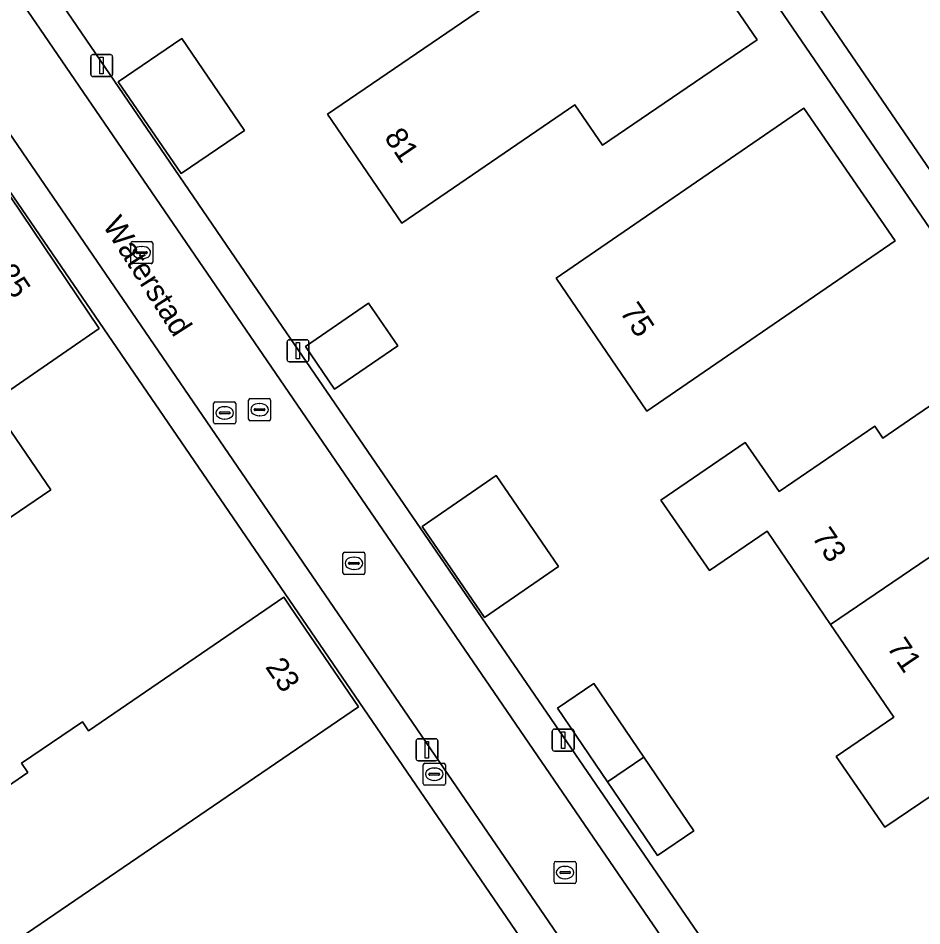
# Model space of a CAD drawing. Extents: x 155275 to 156265, y 382654 to 383635.
# Drawn here: x 155646.86 to 155687.84, y 383354.97 to 383396.14 of the extents above; entities that cross this region are included whole.
import ezdxf

# ---------------------------------------------------------------- set-up
doc = ezdxf.new("R2010")
doc.units = 0
for name, color, linetype in [('IMGEO_Brandkraan', 7, 'Continuous'), ('IMGEO_Erf', 7, 'Continuous'), ('IMGEO_Groenvoorziening', 7, 'Continuous'), ('IMGEO_Kolk', 7, 'Continuous'), ('IMGEO_Lichtmast', 7, 'Continuous'), ('IMGEO_Openbare_ruimte_label', 7, 'Continuous'), ('IMGEO_Pand', 7, 'Continuous'), ('IMGEO_Pand_nummerreeks', 7, 'Continuous'), ('IMGEO_Rijbaan_lokaal_open', 7, 'Continuous'), ('IMGEO_Rioolput', 7, 'Continuous'), ('IMGEO_Voetpad_open', 7, 'Continuous')]:
    doc.layers.add(name, color=color, linetype=linetype)

msp = doc.modelspace()

# ---------------------------------------------------------------- linework, layer by layer
at = {"layer": 'IMGEO_Brandkraan'}
for p, q in [((155665.23, 383361.42), (155665.23, 383362.272)), ((155665.305, 383362.346), (155666.157, 383362.346)), ((155665.718, 383362.126), (155665.743, 383362.126)), ((155666.231, 383362.272), (155666.231, 383361.42)), ((155665.489, 383361.84), (155665.489, 383361.852)), ((155665.927, 383361.803), (155665.529, 383361.803)), ((155665.532, 383361.889), (155665.93, 383361.889)), ((155665.973, 383361.852), (155665.973, 383361.84)), ((155666.157, 383361.346), (155665.305, 383361.346)), ((155665.741, 383361.566), (155665.716, 383361.566))]:
    msp.add_line(p, q, dxfattribs=at)
for points in [[(155665.23, 383361.42), (155665.23, 383362.272)], [(155665.305, 383362.346), (155666.157, 383362.346)], [(155666.231, 383362.272), (155666.231, 383361.42)], [(155666.157, 383361.346), (155665.305, 383361.346)]]:
    msp.add_lwpolyline(points, dxfattribs=at)
for centre, radius, start, end in [((155665.307, 383362.27), 0.0765, 91.552, 178.448), ((155665.307, 383362.27), 0.0765, 91.552, 178.448), ((155666.155, 383362.27), 0.0765, 1.552, 88.448), ((155666.155, 383362.27), 0.0765, 1.552, 88.448), ((155665.529, 383361.849), 0.0403, 85.8775, 175.7526), ((155665.526, 383361.839), 0.0366, 178.938, 274.7102), ((155665.93, 383361.846), 0.043, 264.8664, 352.4533), ((155665.934, 383361.851), 0.0386, 1.7309, 96.639), ((155665.307, 383361.422), 0.0765, 181.552, 268.448), ((155665.307, 383361.422), 0.0765, 181.552, 268.448), ((155666.155, 383361.422), 0.0765, 271.552, 358.448), ((155666.155, 383361.422), 0.0765, 271.552, 358.448)]:
    msp.add_arc(centre, radius, start, end, dxfattribs=at)
for centre, major_axis, ratio, start_param, end_param in [((155665.717, 383361.846), (-0.387, 0.002), 0.722429, 4.712389, 7.853982), ((155665.742, 383361.846), (-0.39, 0.002), 0.717154, 1.570796, 4.712389)]:
    msp.add_ellipse(centre, major_axis=major_axis, ratio=ratio, start_param=start_param, end_param=end_param, dxfattribs=at)
at = {"layer": 'IMGEO_Erf'}
for points in [[(155657.299, 383431.777), (155657.022, 383432.185), (155634.905, 383417.186), (155657.35, 383384.321), (155685.798, 383342.799), (155707.917, 383357.778), (155706.87, 383359.32)], [(155626.344, 383411.364), (155605.932, 383397.438), (155603.987, 383396.057), (155605.754, 383393.471), (155605.827, 383393.52), (155653.992, 383322.86), (155654.882, 383321.57), (155677.497, 383337.038), (155680.25, 383338.906), (155654.839, 383376.063), (155629.299, 383413.395)], [(155664.262, 383386.851), (155660.887, 383391.796), (155675.749, 383401.941), (155680.373, 383395.166), (155673.358, 383390.385), (155672.109, 383392.206)], [(155654.245, 383389.095), (155651.394, 383393.258), (155654.285, 383395.225), (155657.124, 383391.055)], [(155682.494, 383392.068), (155686.631, 383386.042), (155675.363, 383378.324), (155671.25, 383384.356)], [(155632.183, 383363.753), (155632.091, 383363.899), (155632.39, 383364.102), (155630.323, 383367.106), (155630.036, 383366.909), (155627.855, 383370.095), (155632.678, 383373.378), (155633.279, 383372.507), (155634.699, 383373.478), (155644.215, 383379.981), (155641.198, 383384.398), (155646.515, 383388.036), (155650.539, 383382.066), (155645.636, 383378.694), (155648.345, 383374.745)], [(155664.07, 383381.278), (155661.206, 383379.32), (155659.882, 383381.255), (155662.749, 383383.21)], [(155676.001, 383374.285), (155679.826, 383376.894), (155681.363, 383374.67), (155685.708, 383377.643), (155686.078, 383377.098), (155687.286, 383377.925), (155690.617, 383380.203), (155693.821, 383375.522), (155695.296, 383373.366), (155695.031, 383373.186), (155696.707, 383370.712), (155693.642, 383368.618), (155692.452, 383367.806), (155692.81, 383367.255), (155688.46, 383364.27), (155689.99, 383362.038), (155686.157, 383359.44), (155683.96, 383362.652), (155686.568, 383364.436), (155683.705, 383368.644), (155680.832, 383372.872), (155678.207, 383371.082)], [(155668.529, 383375.397), (155671.368, 383371.269), (155668.001, 383368.953), (155665.175, 383373.09)], [(155647.303, 383361.927), (155647.013, 383362.352), (155649.769, 383364.231), (155650.055, 383363.812), (155658.911, 383369.873), (155659.212, 383369.426), (155662.297, 383364.905), (155645.369, 383353.349), (155644.717, 383354.302), (155643.781, 383353.657), (155643.882, 383353.509), (155641.508, 383351.891), (155638.669, 383356.028), (155637.151, 383358.24), (155637.284, 383358.325), (155636.638, 383359.304), (155639.894, 383361.521), (155641.364, 383360.503), (155643.288, 383359.179)], [(155672.969, 383365.966), (155675.238, 383362.624), (155677.508, 383359.282), (155675.853, 383358.158), (155673.584, 383361.5), (155671.314, 383364.843)]]:
    msp.add_lwpolyline(points, close=True, dxfattribs=at)
at = {"layer": 'IMGEO_Groenvoorziening'}
msp.add_lwpolyline([(155671.715, 383413.396), (155689.641, 383387.16), (155697.682, 383392.701), (155680.127, 383418.418), (155674.678, 383414.539), (155674.299, 383415.086)], close=True, dxfattribs=at)
at = {"layer": 'IMGEO_Kolk'}
for p, q in [((155652.039, 383386.008), (155652.891, 383386.008)), ((155651.964, 383385.082), (155651.964, 383385.934)), ((155652.452, 383385.788), (155652.477, 383385.788)), ((155652.965, 383385.934), (155652.965, 383385.082)), ((155652.223, 383385.502), (155652.223, 383385.514)), ((155652.661, 383385.465), (155652.263, 383385.465)), ((155652.266, 383385.551), (155652.664, 383385.551)), ((155652.475, 383385.228), (155652.45, 383385.228)), ((155652.707, 383385.514), (155652.707, 383385.502)), ((155652.891, 383385.008), (155652.039, 383385.008)), ((155661.586, 383370.989), (155661.586, 383371.841)), ((155661.661, 383371.915), (155662.513, 383371.915)), ((155662.074, 383371.695), (155662.099, 383371.695)), ((155662.587, 383371.841), (155662.587, 383370.989)), ((155661.845, 383371.409), (155661.845, 383371.421)), ((155662.283, 383371.372), (155661.885, 383371.372)), ((155661.888, 383371.458), (155662.286, 383371.458)), ((155662.329, 383371.421), (155662.329, 383371.409)), ((155662.513, 383370.915), (155661.661, 383370.915)), ((155662.097, 383371.135), (155662.072, 383371.135)), ((155671.161, 383356.963), (155671.161, 383357.815)), ((155671.236, 383357.889), (155672.088, 383357.889)), ((155671.649, 383357.669), (155671.674, 383357.669)), ((155672.162, 383357.815), (155672.162, 383356.963)), ((155671.42, 383357.383), (155671.42, 383357.395)), ((155671.858, 383357.346), (155671.46, 383357.346)), ((155671.463, 383357.432), (155671.861, 383357.432)), ((155671.904, 383357.395), (155671.904, 383357.383)), ((155672.088, 383356.889), (155671.236, 383356.889)), ((155671.672, 383357.109), (155671.647, 383357.109))]:
    msp.add_line(p, q, dxfattribs=at)
for points in [[(155652.039, 383386.008), (155652.891, 383386.008)], [(155651.964, 383385.082), (155651.964, 383385.934)], [(155652.965, 383385.934), (155652.965, 383385.082)], [(155652.891, 383385.008), (155652.039, 383385.008)], [(155661.586, 383370.989), (155661.586, 383371.841)], [(155661.661, 383371.915), (155662.513, 383371.915)], [(155662.587, 383371.841), (155662.587, 383370.989)], [(155662.513, 383370.915), (155661.661, 383370.915)], [(155671.161, 383356.963), (155671.161, 383357.815)], [(155671.236, 383357.889), (155672.088, 383357.889)], [(155672.162, 383357.815), (155672.162, 383356.963)], [(155672.088, 383356.889), (155671.236, 383356.889)]]:
    msp.add_lwpolyline(points, dxfattribs=at)
for centre, radius, start, end in [((155652.041, 383385.932), 0.0765, 91.552, 178.448), ((155652.041, 383385.932), 0.0765, 91.552, 178.448), ((155652.889, 383385.932), 0.0765, 1.552, 88.448), ((155652.889, 383385.932), 0.0765, 1.552, 88.448), ((155652.263, 383385.511), 0.0403, 85.8775, 175.7526), ((155652.26, 383385.501), 0.0366, 178.938, 274.7102), ((155652.664, 383385.508), 0.043, 264.8664, 352.4533), ((155652.668, 383385.513), 0.0386, 1.7309, 96.639), ((155652.041, 383385.084), 0.0765, 181.552, 268.448), ((155652.041, 383385.084), 0.0765, 181.552, 268.448), ((155652.889, 383385.084), 0.0765, 271.552, 358.448), ((155652.889, 383385.084), 0.0765, 271.552, 358.448), ((155661.663, 383371.839), 0.0765, 91.552, 178.448), ((155661.663, 383371.839), 0.0765, 91.552, 178.448), ((155662.511, 383371.839), 0.0765, 1.552, 88.448), ((155662.511, 383371.839), 0.0765, 1.552, 88.448), ((155661.885, 383371.418), 0.0403, 85.8775, 175.7526), ((155661.882, 383371.408), 0.0366, 178.938, 274.7102), ((155662.286, 383371.415), 0.043, 264.8664, 352.4533), ((155662.29, 383371.42), 0.0386, 1.7309, 96.639), ((155661.663, 383370.991), 0.0765, 181.552, 268.448), ((155661.663, 383370.991), 0.0765, 181.552, 268.448), ((155662.511, 383370.991), 0.0765, 271.552, 358.448), ((155662.511, 383370.991), 0.0765, 271.552, 358.448), ((155671.238, 383357.813), 0.0765, 91.552, 178.448), ((155671.238, 383357.813), 0.0765, 91.552, 178.448), ((155672.086, 383357.813), 0.0765, 1.552, 88.448), ((155672.086, 383357.813), 0.0765, 1.552, 88.448), ((155671.46, 383357.392), 0.0403, 85.8775, 175.7526), ((155671.457, 383357.382), 0.0366, 178.938, 274.7102), ((155671.861, 383357.389), 0.043, 264.8664, 352.4533), ((155671.865, 383357.394), 0.0386, 1.7309, 96.639), ((155671.238, 383356.965), 0.0765, 181.552, 268.448), ((155671.238, 383356.965), 0.0765, 181.552, 268.448), ((155672.086, 383356.965), 0.0765, 271.552, 358.448), ((155672.086, 383356.965), 0.0765, 271.552, 358.448)]:
    msp.add_arc(centre, radius, start, end, dxfattribs=at)
for centre, major_axis, ratio, start_param, end_param in [((155652.451, 383385.508), (-0.387, 0.002), 0.722429, 4.712389, 7.853982), ((155652.476, 383385.508), (-0.39, 0.002), 0.717154, 1.570796, 4.712389), ((155662.073, 383371.415), (-0.387, 0.002), 0.722429, 4.712389, 7.853982), ((155662.098, 383371.415), (-0.39, 0.002), 0.717154, 1.570796, 4.712389), ((155671.648, 383357.389), (-0.387, 0.002), 0.722429, 4.712389, 7.853982), ((155671.673, 383357.389), (-0.39, 0.002), 0.717154, 1.570796, 4.712389)]:
    msp.add_ellipse(centre, major_axis=major_axis, ratio=ratio, start_param=start_param, end_param=end_param, dxfattribs=at)
at = {"layer": 'IMGEO_Lichtmast'}
for p, q in [((155650.15, 383393.596), (155650.15, 383394.396)), ((155650.15, 383394.396), (155650.15, 383393.596)), ((155650.25, 383394.496), (155651.04, 383394.496)), ((155651.04, 383394.496), (155650.25, 383394.496)), ((155651.14, 383394.396), (155651.14, 383393.596)), ((155651.14, 383393.596), (155651.14, 383394.396)), ((155651.04, 383393.496), (155650.25, 383393.496)), ((155650.25, 383393.496), (155651.04, 383393.496)), ((155659.052, 383380.659), (155659.052, 383381.459)), ((155659.052, 383381.459), (155659.052, 383380.659)), ((155659.152, 383381.559), (155659.942, 383381.559)), ((155659.942, 383381.559), (155659.152, 383381.559)), ((155660.042, 383381.459), (155660.042, 383380.659)), ((155660.042, 383380.659), (155660.042, 383381.459)), ((155659.942, 383380.559), (155659.152, 383380.559)), ((155659.152, 383380.559), (155659.942, 383380.559)), ((155671.079, 383362.994), (155671.079, 383363.794)), ((155671.079, 383363.794), (155671.079, 383362.994)), ((155671.179, 383363.894), (155671.969, 383363.894)), ((155671.969, 383363.894), (155671.179, 383363.894)), ((155672.069, 383363.794), (155672.069, 383362.994)), ((155672.069, 383362.994), (155672.069, 383363.794)), ((155664.902, 383362.556), (155664.902, 383363.356)), ((155664.902, 383363.356), (155664.902, 383362.556)), ((155665.002, 383363.456), (155665.792, 383363.456)), ((155665.792, 383363.456), (155665.002, 383363.456)), ((155665.892, 383363.356), (155665.892, 383362.556)), ((155665.892, 383362.556), (155665.892, 383363.356)), ((155671.969, 383362.894), (155671.179, 383362.894)), ((155671.179, 383362.894), (155671.969, 383362.894)), ((155665.792, 383362.456), (155665.002, 383362.456)), ((155665.002, 383362.456), (155665.792, 383362.456))]:
    msp.add_line(p, q, dxfattribs=at)
for points in [[(155650.57, 383394.371), (155650.72, 383394.371), (155650.72, 383393.621), (155650.57, 383393.621), (155650.57, 383394.371)], [(155659.472, 383381.434), (155659.622, 383381.434), (155659.622, 383380.684), (155659.472, 383380.684), (155659.472, 383381.434)], [(155671.499, 383363.769), (155671.649, 383363.769), (155671.649, 383363.019), (155671.499, 383363.019), (155671.499, 383363.769)], [(155665.322, 383363.331), (155665.472, 383363.331), (155665.472, 383362.581), (155665.322, 383362.581), (155665.322, 383363.331)]]:
    msp.add_lwpolyline(points, dxfattribs=at)
for centre, start, end in [((155650.25, 383394.396), 90, 180), ((155650.25, 383394.396), 90, 180), ((155651.04, 383394.396), 0, 90), ((155651.04, 383394.396), 360, 90), ((155650.25, 383393.596), 180, 270), ((155650.25, 383393.596), 180, 270), ((155651.04, 383393.596), 270, 0), ((155651.04, 383393.596), 270, 0), ((155659.152, 383381.459), 90, 180), ((155659.152, 383381.459), 90, 180), ((155659.942, 383381.459), 0, 90), ((155659.942, 383381.459), 360, 90), ((155659.152, 383380.659), 180, 270), ((155659.152, 383380.659), 180, 270), ((155659.942, 383380.659), 270, 0), ((155659.942, 383380.659), 270, 0), ((155671.179, 383363.794), 90, 180), ((155671.179, 383363.794), 90, 180), ((155671.969, 383363.794), 0, 90), ((155671.969, 383363.794), 360, 90), ((155665.002, 383363.356), 90, 180), ((155665.002, 383363.356), 90, 180), ((155665.792, 383363.356), 0, 90), ((155665.792, 383363.356), 360, 90), ((155671.179, 383362.994), 180, 270), ((155671.179, 383362.994), 180, 270), ((155671.969, 383362.994), 270, 0), ((155671.969, 383362.994), 270, 0), ((155665.002, 383362.556), 180, 270), ((155665.002, 383362.556), 180, 270), ((155665.792, 383362.556), 270, 0), ((155665.792, 383362.556), 270, 0)]:
    msp.add_arc(centre, 0.1, start, end, dxfattribs=at)
at = {"layer": 'IMGEO_Pand'}
for points in [[(155675.749, 383401.941), (155660.887, 383391.796), (155664.262, 383386.851), (155672.109, 383392.206), (155673.358, 383390.385), (155680.373, 383395.166)], [(155654.285, 383395.225), (155651.394, 383393.258), (155654.245, 383389.095), (155657.124, 383391.055)], [(155682.494, 383392.068), (155671.25, 383384.356), (155675.363, 383378.324), (155686.631, 383386.042)], [(155645.636, 383378.694), (155650.539, 383382.066), (155646.515, 383388.036), (155641.198, 383384.398), (155644.215, 383379.981), (155634.699, 383373.478), (155633.279, 383372.507), (155632.678, 383373.378), (155627.855, 383370.095), (155630.036, 383366.909), (155630.323, 383367.106), (155632.39, 383364.102), (155632.091, 383363.899), (155632.183, 383363.753), (155648.345, 383374.745)], [(155662.749, 383383.21), (155659.882, 383381.255), (155661.206, 383379.32), (155664.07, 383381.278)], [(155690.617, 383380.203), (155687.286, 383377.925), (155686.078, 383377.098), (155685.708, 383377.643), (155681.363, 383374.67), (155679.826, 383376.894), (155676.001, 383374.285), (155678.207, 383371.082), (155680.832, 383372.872), (155683.705, 383368.644), (155693.821, 383375.522)], [(155668.529, 383375.397), (155665.175, 383373.09), (155668.001, 383368.953), (155671.368, 383371.269)], [(155696.707, 383370.712), (155695.031, 383373.186), (155695.296, 383373.366), (155693.821, 383375.522), (155683.705, 383368.644), (155686.568, 383364.436), (155683.96, 383362.652), (155686.157, 383359.44), (155689.99, 383362.038), (155688.46, 383364.27), (155692.81, 383367.255), (155692.452, 383367.806), (155693.642, 383368.618)], [(155662.297, 383364.905), (155659.212, 383369.426), (155658.911, 383369.873), (155650.055, 383363.812), (155649.769, 383364.231), (155647.013, 383362.352), (155647.303, 383361.927), (155643.288, 383359.179), (155641.364, 383360.503), (155639.894, 383361.521), (155636.638, 383359.304), (155637.284, 383358.325), (155637.151, 383358.24), (155638.669, 383356.028), (155641.508, 383351.891), (155643.882, 383353.509), (155643.781, 383353.657), (155644.717, 383354.302), (155645.369, 383353.349)], [(155671.314, 383364.843), (155673.584, 383361.5), (155675.238, 383362.624), (155672.969, 383365.966)], [(155675.238, 383362.624), (155673.584, 383361.5), (155675.853, 383358.158), (155677.508, 383359.282)]]:
    msp.add_lwpolyline(points, close=True, dxfattribs=at)
at = {"layer": 'IMGEO_Rijbaan_lokaal_open'}
for points in [[(155629.214, 383416.139), (155630.534, 383414.209), (155681.461, 383339.737), (155682.726, 383337.887)], [(155685.887, 383340.048), (155684.569, 383341.975), (155633.677, 383416.365)]]:
    msp.add_lwpolyline(points, dxfattribs=at)
at = {"layer": 'IMGEO_Rioolput'}
for p, q in [((155655.724, 383377.811), (155655.724, 383378.663)), ((155655.799, 383378.737), (155656.651, 383378.737)), ((155656.725, 383378.663), (155656.725, 383377.811)), ((155657.308, 383377.959), (155657.308, 383378.811)), ((155657.383, 383378.885), (155658.235, 383378.885)), ((155657.796, 383378.665), (155657.821, 383378.665)), ((155658.309, 383378.811), (155658.309, 383377.959)), ((155655.983, 383378.231), (155655.983, 383378.243)), ((155656.421, 383378.194), (155656.023, 383378.194)), ((155656.026, 383378.28), (155656.424, 383378.28)), ((155656.212, 383378.517), (155656.237, 383378.517)), ((155656.467, 383378.243), (155656.467, 383378.231)), ((155657.567, 383378.379), (155657.567, 383378.391)), ((155658.005, 383378.342), (155657.607, 383378.342)), ((155657.61, 383378.428), (155658.008, 383378.428)), ((155658.051, 383378.391), (155658.051, 383378.379)), ((155656.235, 383377.957), (155656.21, 383377.957)), ((155658.235, 383377.885), (155657.383, 383377.885)), ((155657.819, 383378.105), (155657.794, 383378.105)), ((155656.651, 383377.737), (155655.799, 383377.737))]:
    msp.add_line(p, q, dxfattribs=at)
for points in [[(155655.724, 383377.811), (155655.724, 383378.663)], [(155655.799, 383378.737), (155656.651, 383378.737)], [(155656.725, 383378.663), (155656.725, 383377.811)], [(155657.308, 383377.959), (155657.308, 383378.811)], [(155657.383, 383378.885), (155658.235, 383378.885)], [(155658.309, 383378.811), (155658.309, 383377.959)], [(155658.235, 383377.885), (155657.383, 383377.885)], [(155656.651, 383377.737), (155655.799, 383377.737)]]:
    msp.add_lwpolyline(points, dxfattribs=at)
for centre, radius, start, end in [((155655.801, 383378.661), 0.0765, 91.552, 178.448), ((155655.801, 383378.661), 0.0765, 91.552, 178.448), ((155656.649, 383378.661), 0.0765, 1.552, 88.448), ((155656.649, 383378.661), 0.0765, 1.552, 88.448), ((155657.385, 383378.809), 0.0765, 91.552, 178.448), ((155657.385, 383378.809), 0.0765, 91.552, 178.448), ((155658.233, 383378.809), 0.0765, 1.552, 88.448), ((155658.233, 383378.809), 0.0765, 1.552, 88.448), ((155656.023, 383378.24), 0.0403, 85.8775, 175.7526), ((155656.02, 383378.23), 0.0366, 178.938, 274.7102), ((155656.424, 383378.237), 0.043, 264.8664, 352.4533), ((155656.428, 383378.242), 0.0386, 1.7309, 96.639), ((155657.607, 383378.388), 0.0403, 85.8775, 175.7526), ((155657.604, 383378.378), 0.0366, 178.938, 274.7102), ((155658.008, 383378.385), 0.043, 264.8664, 352.4533), ((155658.012, 383378.39), 0.0386, 1.7309, 96.639), ((155655.801, 383377.813), 0.0765, 181.552, 268.448), ((155655.801, 383377.813), 0.0765, 181.552, 268.448), ((155656.649, 383377.813), 0.0765, 271.552, 358.448), ((155656.649, 383377.813), 0.0765, 271.552, 358.448), ((155657.385, 383377.961), 0.0765, 181.552, 268.448), ((155657.385, 383377.961), 0.0765, 181.552, 268.448), ((155658.233, 383377.961), 0.0765, 271.552, 358.448), ((155658.233, 383377.961), 0.0765, 271.552, 358.448)]:
    msp.add_arc(centre, radius, start, end, dxfattribs=at)
for centre, major_axis, ratio, start_param, end_param in [((155657.795, 383378.385), (-0.387, 0.002), 0.722429, 4.712389, 7.853982), ((155657.82, 383378.385), (-0.39, 0.002), 0.717154, 1.570796, 4.712389), ((155656.211, 383378.237), (-0.387, 0.002), 0.722429, 4.712389, 7.853982), ((155656.236, 383378.237), (-0.39, 0.002), 0.717154, 1.570796, 4.712389)]:
    msp.add_ellipse(centre, major_axis=major_axis, ratio=ratio, start_param=start_param, end_param=end_param, dxfattribs=at)
at = {"layer": 'IMGEO_Voetpad_open'}
msp.add_lwpolyline([(155657.299, 383431.777), (155706.87, 383359.32), (155707.917, 383357.778), (155708.636, 383356.718), (155708.663, 383356.678), (155711.009, 383353.222), (155711.461, 383352.556), (155712.721, 383353.417), (155709.882, 383357.573), (155717.961, 383363.071), (155720.795, 383358.936), (155720.939, 383359.034), (155722.109, 383359.832), (155721.652, 383360.486), (155719.23, 383363.961), (155718.509, 383364.995), (155691.786, 383403.993)], dxfattribs=at)
for points in [[(155689.641, 383387.16), (155671.715, 383413.396), (155674.299, 383415.086), (155674.678, 383414.539), (155680.127, 383418.418), (155697.682, 383392.701)], [(155634.905, 383417.186), (155633.677, 383416.365), (155684.569, 383341.975), (155685.798, 383342.799), (155657.35, 383384.321)], [(155630.534, 383414.209), (155629.299, 383413.395), (155654.839, 383376.063), (155680.25, 383338.906), (155681.461, 383339.737)]]:
    msp.add_lwpolyline(points, close=True, dxfattribs=at)

# ---------------------------------------------------------------- texts
at = {"layer": 'IMGEO_Openbare_ruimte_label'}
msp.add_text('Waterstad', height=1, rotation=302.625, dxfattribs=at).set_placement((155650.662, 383386.751))
at = {"layer": 'IMGEO_Pand_nummerreeks'}
for s, rotation, p in [('81', 304.1137, (155663.431, 383390.736)), ('25', 303.7814, (155645.827, 383384.589)), ('75', 304.0908, (155674.118, 383382.818)), ('73', 303.9991, (155682.827, 383372.609)), ('71', 304.0335, (155686.229, 383367.606)), ('23', 304.108, (155658.04, 383366.714))]:
    msp.add_text(s, height=1, rotation=rotation, dxfattribs=at).set_placement(p)

doc.saveas('drawing.dxf')
